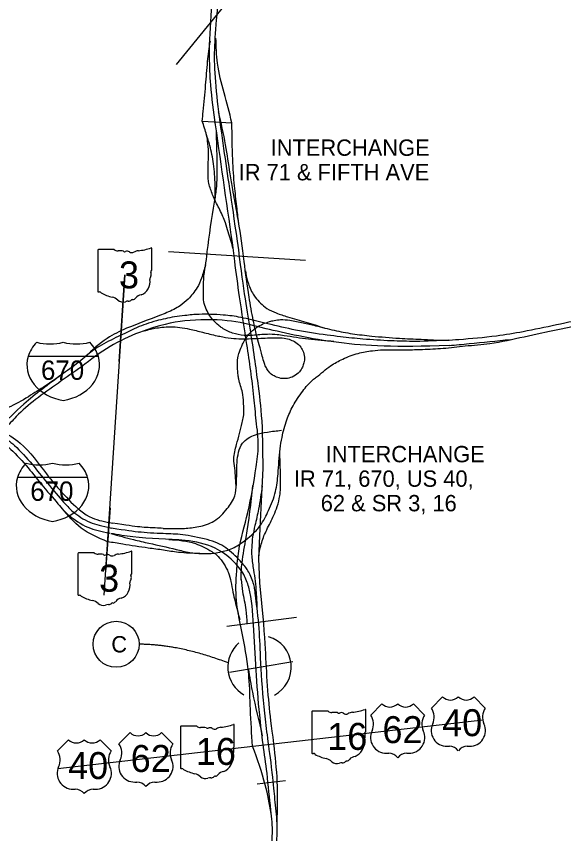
# Model space of a CAD drawing. Extents: x -13 to 322, y -402 to 112.
# Drawn here: x 2.19 to 6.02, y 100.58 to 106.3 of the extents above; entities that cross this region are included whole.
import ezdxf

# ---------------------------------------------------------------- set-up
doc = ezdxf.new("R2010")
doc.units = 0
for name, color, linetype in [('GM_X_Interstate_Shield', 7, 'Continuous'), ('GM_X_State_Shield', 7, 'Continuous'), ('GM_X_US_Shield', 7, 'Continuous'), ('SC_Scratch1', 7, 'Continuous'), ('SH_Data', 7, 'Continuous'), ('SH_Text', 7, 'Continuous')]:
    doc.layers.add(name, color=color, linetype=linetype)

msp = doc.modelspace()

# ---------------------------------------------------------------- linework, layer by layer
at = {"layer": 'GM_X_Interstate_Shield'}
for p, q in [((2.7633, 103.9213), (2.2717, 103.9213)), ((2.7633, 103.9213), (2.2717, 103.9213)), ((2.6884, 103.0745), (2.1967, 103.0745)), ((2.6884, 103.0745), (2.1967, 103.0745))]:
    msp.add_line(p, q, dxfattribs=at)
for centre, start_param, end_param in [((2.581, 103.8632), 2.47259, 2.911027), ((2.4246, 104.264), 4.415841, 5.008937), ((2.6103, 104.264), 4.415841, 5.008937), ((2.4539, 103.8632), 0.230566, 0.669003), ((2.581, 103.8632), 2.911027, 4.511031), ((2.4539, 103.8632), 4.913747, 6.513751), ((2.5061, 103.0164), 2.47259, 2.911027), ((2.3497, 103.4172), 4.415841, 5.008937), ((2.5354, 103.4172), 4.415841, 5.008937), ((2.379, 103.0164), 0.230566, 0.669003), ((2.5061, 103.0164), 2.911027, 4.511031), ((2.379, 103.0164), 4.913747, 6.513751)]:
    msp.add_ellipse(centre, major_axis=(0.3178, 0), ratio=0.8, start_param=start_param, end_param=end_param, dxfattribs=at)
at = {"layer": 'GM_X_State_Shield'}
for p, q in [((2.7595, 104.6646), (2.7595, 104.3781)), ((2.8738, 104.6695), (2.7632, 104.6695)), ((3.137, 104.5267), (3.137, 104.6766)), ((3.137, 104.5268), (3.137, 104.5267)), ((2.6204, 102.5415), (2.6204, 102.255)), ((2.7346, 102.5465), (2.6241, 102.5465)), ((2.9979, 102.4037), (2.9979, 102.5536)), ((2.9978, 102.4037), (2.9979, 102.4037)), ((4.2575, 101.4346), (4.2575, 101.1481)), ((4.3718, 101.4396), (4.2612, 101.4396)), ((4.635, 101.2968), (4.635, 101.4467)), ((3.3375, 101.3293), (3.3375, 101.0427)), ((3.4518, 101.3342), (3.3412, 101.3342)), ((3.715, 101.1914), (3.715, 101.3413)), ((4.635, 101.2968), (4.635, 101.2968)), ((3.715, 101.1914), (3.715, 101.1914))]:
    msp.add_line(p, q, dxfattribs=at)
for centre, radius, start, end in [((3.0025, 105.0601), 0.4003, 275.8445, 288.9065), ((3.1328, 104.6772), 0.0042, 351.8621, 97.738), ((2.7638, 104.6652), 0.00437, 98.1301, 188.1301), ((2.9001, 104.7028), 0.0424, 231.6195, 271.1119), ((2.9142, 104.5087), 0.1523, 80.4867, 94.9883), ((2.9487, 104.6667), 0.0122, 219.7921, 297.1024), ((2.9667, 104.6336), 0.0254, 54.4667, 119.1411), ((2.9995, 104.679), 0.0306, 233.8562, 294.8282), ((3.0536, 104.582), 0.0805, 97.3462, 120.7689), ((3.136, 104.5157), 0.0065, 107.944, 210.337), ((3.0947, 104.4968), 0.039, 340.033, 23.6496), ((3.1325, 104.5261), 0.0045, 289.6038, 7.7341), ((3.025, 104.4449), 0.1001, 292.3089, 8.9858), ((3.1521, 104.464), 0.0284, 136.8065, 186.9296), ((2.7639, 104.3774), 0.00441, 171.9584, 258.3066), ((2.7645, 104.4067), 0.0337, 267.339, 280.6039), ((2.7714, 104.3615), 0.0121, 29.7484, 93.2717), ((2.9247, 104.619), 0.2891, 240.4129, 257.1985), ((2.8385, 104.2493), 0.0905, 47.1842, 75.836), ((3.0672, 104.2976), 0.0548, 94.4031, 142.5768), ((2.9363, 104.3601), 0.0574, 230.7004, 286.2918), ((2.9695, 104.2611), 0.0472, 85.6951, 111.2099), ((2.9737, 104.3387), 0.0306, 268.777, 315.5493), ((3.0014, 104.3109), 0.00861, 65.7517, 132.6484), ((2.9977, 104.3503), 0.0324, 282.8732, 323.2771), ((2.6247, 102.5421), 0.00437, 98.1301, 188.1301), ((2.761, 102.5797), 0.0424, 231.6195, 271.1119), ((2.775, 102.3856), 0.1523, 80.4867, 94.9883), ((2.8096, 102.5436), 0.0122, 219.7921, 297.1024), ((2.8276, 102.5105), 0.0254, 54.4667, 119.1411), ((2.8604, 102.5559), 0.0306, 233.8562, 294.8282), ((2.9145, 102.459), 0.0805, 97.3462, 120.7689), ((2.8634, 102.9371), 0.4003, 275.8445, 288.9065), ((2.9937, 102.5542), 0.0042, 351.8621, 97.738), ((2.9969, 102.3927), 0.0065, 107.944, 210.337), ((2.9934, 102.4031), 0.0045, 289.6038, 7.7341), ((2.8858, 102.3219), 0.1001, 292.3089, 8.9858), ((3.0129, 102.341), 0.0284, 136.8065, 186.9296), ((2.9555, 102.3737), 0.039, 340.033, 23.6496), ((2.6247, 102.2544), 0.00441, 171.9584, 258.3066), ((2.6254, 102.2837), 0.0337, 267.339, 280.6039), ((2.6323, 102.2385), 0.0121, 29.7484, 93.2717), ((2.7856, 102.4959), 0.2891, 240.4129, 257.1985), ((2.928, 102.1746), 0.0548, 94.4031, 142.5768), ((2.6994, 102.1263), 0.0905, 47.1842, 75.836), ((2.7972, 102.2371), 0.0574, 230.7004, 286.2918), ((2.8304, 102.138), 0.0472, 85.6951, 111.2099), ((2.8346, 102.2156), 0.0306, 268.777, 315.5493), ((2.8622, 102.1879), 0.00861, 65.7517, 132.6484), ((2.8586, 102.2273), 0.0324, 282.8732, 323.2771), ((4.2619, 101.4353), 0.00437, 98.1301, 188.1301), ((4.3981, 101.4728), 0.0424, 231.6195, 271.1119), ((4.4122, 101.2787), 0.1523, 80.4867, 94.9883), ((4.4468, 101.4367), 0.0122, 219.7921, 297.1024), ((4.4647, 101.4036), 0.0254, 54.4667, 119.1411), ((4.4976, 101.449), 0.0306, 233.8562, 294.8282), ((4.5516, 101.3521), 0.0805, 97.3462, 120.7689), ((4.5006, 101.8302), 0.4003, 275.8445, 288.9065), ((4.6308, 101.4473), 0.0042, 351.8621, 97.738), ((3.3419, 101.3299), 0.00437, 98.1301, 188.1301), ((3.4781, 101.3675), 0.0424, 231.6195, 271.1119), ((3.4922, 101.1733), 0.1523, 80.4867, 94.9883), ((3.5268, 101.3314), 0.0122, 219.7921, 297.1024), ((3.5447, 101.2982), 0.0254, 54.4667, 119.1411), ((3.5776, 101.3437), 0.0306, 233.8562, 294.8282), ((3.6316, 101.2467), 0.0805, 97.3462, 120.7689), ((3.5806, 101.7248), 0.4003, 275.8445, 288.9065), ((3.7108, 101.3419), 0.0042, 351.8621, 97.738), ((4.6501, 101.2341), 0.0284, 136.8065, 186.9296), ((4.6341, 101.2858), 0.0065, 107.944, 210.337), ((4.5927, 101.2668), 0.039, 340.033, 23.6496), ((4.6305, 101.2962), 0.0045, 289.6038, 7.7341), ((3.7105, 101.1908), 0.0045, 289.6038, 7.7341), ((4.523, 101.215), 0.1001, 292.3089, 8.9858), ((3.7301, 101.1287), 0.0284, 136.8065, 186.9296), ((3.7141, 101.1804), 0.0065, 107.944, 210.337), ((3.6727, 101.1615), 0.039, 340.033, 23.6496), ((4.2619, 101.1475), 0.00441, 171.9584, 258.3066), ((4.2626, 101.1768), 0.0337, 267.339, 280.6039), ((4.2695, 101.1316), 0.0121, 29.7484, 93.2717), ((4.4227, 101.389), 0.2891, 240.4129, 257.1985), ((3.603, 101.1096), 0.1001, 292.3089, 8.9858), ((4.3365, 101.0194), 0.0905, 47.1842, 75.836), ((4.4344, 101.1302), 0.0574, 230.7004, 286.2918), ((4.4675, 101.0311), 0.0472, 85.6951, 111.2099), ((4.4717, 101.1087), 0.0306, 268.777, 315.5493), ((4.4994, 101.081), 0.00861, 65.7517, 132.6484), ((4.4957, 101.1204), 0.0324, 282.8732, 323.2771), ((4.5652, 101.0677), 0.0548, 94.4031, 142.5768), ((3.3419, 101.0421), 0.00441, 171.9584, 258.3066), ((3.3426, 101.0714), 0.0337, 267.339, 280.6039), ((3.3494, 101.0262), 0.0121, 29.7484, 93.2717), ((3.5027, 101.2836), 0.2891, 240.4129, 257.1985), ((3.4165, 100.914), 0.0905, 47.1842, 75.836), ((3.5144, 101.0248), 0.0574, 230.7004, 286.2918), ((3.5475, 100.9257), 0.0472, 85.6951, 111.2099), ((3.5517, 101.0033), 0.0306, 268.777, 315.5493), ((3.5794, 100.9756), 0.00861, 65.7517, 132.6484), ((3.5757, 101.015), 0.0324, 282.8732, 323.2771), ((3.6452, 100.9623), 0.0548, 94.4031, 142.5768)]:
    msp.add_arc(centre, radius, start, end, dxfattribs=at)
at = {"layer": 'GM_X_US_Shield'}
for p, q in [((5.1733, 101.5395), (5.0947, 101.4608)), ((5.4722, 101.4608), (5.3935, 101.5395)), ((4.7487, 101.4908), (4.6701, 101.4122)), ((5.0476, 101.4122), (4.969, 101.4908)), ((2.9861, 101.2889), (2.9075, 101.2103)), ((3.285, 101.2103), (3.2063, 101.2889)), ((2.5547, 101.2395), (2.4761, 101.1609)), ((2.8536, 101.1609), (2.7749, 101.2395)), ((5.2048, 101.1934), (5.2205, 101.1934)), ((5.3464, 101.1934), (5.3621, 101.1934)), ((4.7802, 101.1448), (4.7959, 101.1448)), ((4.9218, 101.1448), (4.9375, 101.1448)), ((3.0176, 100.9429), (3.0333, 100.9429)), ((3.1592, 100.9429), (3.1749, 100.9429)), ((2.5862, 100.8935), (2.6019, 100.8935)), ((2.7277, 100.8935), (2.7434, 100.8935))]:
    msp.add_line(p, q, dxfattribs=at)
for centre, radius, start, end in [((5.2284, 101.5956), 0.0786, 225.573, 314.427), ((5.3385, 101.5956), 0.0786, 225.573, 314.427), ((4.8038, 101.547), 0.0786, 225.573, 314.427), ((4.9139, 101.547), 0.0786, 225.573, 314.427), ((5.0045, 101.3977), 0.1101, 334.5471, 35.0009), ((5.5624, 101.3977), 0.1101, 144.9991, 205.4529), ((4.5799, 101.349), 0.1101, 334.5471, 35.0009), ((5.1378, 101.349), 0.1101, 144.9991, 205.4529), ((5.2036, 101.3035), 0.1101, 154.8319, 270.6383), ((5.3633, 101.3035), 0.1101, 269.3617, 25.1681), ((3.0412, 101.3451), 0.0786, 225.573, 314.427), ((3.1513, 101.3451), 0.0786, 225.573, 314.427), ((4.779, 101.2549), 0.1101, 154.8319, 270.6383), ((4.9387, 101.2549), 0.1101, 269.3617, 25.1681), ((2.6097, 101.2957), 0.0786, 225.573, 314.427), ((2.7199, 101.2957), 0.0786, 225.573, 314.427), ((2.8173, 101.1471), 0.1101, 334.5471, 35.0009), ((3.3752, 101.1471), 0.1101, 144.9991, 205.4529), ((5.2205, 101.1148), 0.0786, 36.8699, 90), ((5.3464, 101.1148), 0.0786, 90, 143.1301), ((2.3859, 101.0977), 0.1101, 334.5471, 35.0009), ((2.9437, 101.0977), 0.1101, 144.9991, 205.4529), ((4.7959, 101.0661), 0.0786, 36.8699, 90), ((4.9218, 101.0661), 0.0786, 90, 143.1301), ((3.0164, 101.053), 0.1101, 154.8319, 270.6383), ((3.1761, 101.053), 0.1101, 269.3617, 25.1681), ((2.5849, 101.0036), 0.1101, 154.8319, 270.6383), ((2.7447, 101.0036), 0.1101, 269.3617, 25.1681), ((3.0333, 100.8642), 0.0786, 36.8699, 90), ((3.1592, 100.8642), 0.0786, 90, 143.1301), ((2.6019, 100.8148), 0.0786, 36.8699, 90), ((2.7277, 100.8148), 0.0786, 90, 143.1301)]:
    msp.add_arc(centre, radius, start, end, dxfattribs=at)
at = {"layer": 'SC_Scratch1'}
for p, q in [((3.9038, 106.6966), (3.3082, 105.9659)), ((3.2542, 104.6557), (4.2144, 104.5967)), ((2.91, 103.8855), (2.9485, 104.4926)), ((2.845, 102.863), (2.8124, 102.4156)), ((3.6616, 102.0342), (4.1516, 102.0974)), ((3.6807, 101.713), (4.125, 101.7859)), ((3.8743, 100.9305), (4.0741, 100.9547))]:
    msp.add_line(p, q, dxfattribs=at)
at = {"layer": 'SH_Data'}
for p, q in [((3.4903, 105.568), (3.6984, 105.5575)), ((2.9485, 104.4926), (2.8017, 102.2512)), ((3.9162, 103.1378), (3.9127, 103.4251)), ((3.9074, 102.9553), (3.9162, 103.1378)), ((3.8958, 102.717), (3.9074, 102.9553)), ((3.8856, 102.5067), (3.8958, 102.717)), ((3.8928, 102.3373), (3.8856, 102.5067)), ((3.921, 102.0537), (3.8928, 102.3373)), ((2.4802, 101.0375), (5.454, 101.3781))]:
    msp.add_line(p, q, dxfattribs=at)
msp.add_circle((2.8876, 101.9075), 0.1612, dxfattribs=at)
for start, end in [(297.8961, 73.2622), (130.6141, 240.4143)]:
    msp.add_arc((3.8916, 101.7479), 0.2221, start, end, dxfattribs=at)
for points in [[(3.7092, 104.6637), (3.5843, 105.5418), (3.5502, 105.8224), (3.5419, 106.018), (3.5884, 106.6724), (3.6232, 107.0317), (3.6255, 107.0682), (3.6713, 107.6752), (3.713, 108.1683), (3.7189, 108.3717), (3.7325, 109.1742), (3.7325, 109.2177), (3.7156, 109.4217), (3.6709, 109.6129), (3.5578, 109.8519), (3.4048, 110.0687), (3.2534, 110.2041), (2.9985, 110.3714), (2.7278, 110.5625), (2.5969, 110.6787), (2.4431, 110.8702), (2.3082, 111.1041), (2.2413, 111.2745), (2.1732, 111.5886), (2.143, 111.8754)], [(3.4903, 105.568), (3.497, 105.6372), (3.5145, 105.8198), (3.5285, 105.9868), (3.5473, 106.1278)], [(3.6984, 105.5575), (3.6441, 105.7663), (3.5969, 105.9737), (3.5868, 106.1503)], [(3.0732, 104.098), (3.1598, 104.1192), (3.2075, 104.1264), (3.2695, 104.1301), (3.3329, 104.1255), (3.4024, 104.1134), (3.4934, 104.0911), (3.5942, 104.0669), (3.6336, 104.059), (3.7118, 104.0481), (3.8486, 104.0471), (3.8863, 104.0486), (4.0082, 104.0531), (4.0636, 104.05), (4.1092, 104.0381), (4.1459, 104.0202), (4.1806, 103.9861), (4.1984, 103.9529), (4.2059, 103.9041), (4.2003, 103.8694), (4.1887, 103.8409), (4.1628, 103.8056), (4.1193, 103.778), (4.0758, 103.7671), (4.0285, 103.7711), (3.9935, 103.7852), (3.9562, 103.8162), (3.9396, 103.8412), (3.9253, 103.8735), (3.9105, 103.9248), (3.8902, 104.0021), (3.8714, 104.0713), (3.8598, 104.1181), (3.8478, 104.1735), (3.8182, 104.3378), (3.784, 104.5863), (3.775, 104.6615), (3.7319, 104.9368), (3.7039, 105.0899), (3.6859, 105.2003), (3.6543, 105.4025), (3.6053, 105.6351)], [(3.7077, 104.6747), (3.6728, 104.7931), (3.6528, 104.8568), (3.6354, 104.9024), (3.5908, 104.9923), (3.5633, 105.0539), (3.5486, 105.0921), (3.5366, 105.1336), (3.5319, 105.1732), (3.5319, 105.2551), (3.534, 105.3505), (3.5282, 105.4311), (3.5202, 105.4728), (3.4903, 105.568)], [(3.745, 104.8597), (3.7325, 104.9717), (3.7167, 105.115), (3.7041, 105.3001), (3.6984, 105.5575)], [(4.4127, 104.0269), (4.2334, 104.0423), (4.1499, 104.0541), (4.0637, 104.0671), (4.0153, 104.0739), (3.9464, 104.0766), (3.8428, 104.0695), (3.7837, 104.0695), (3.7023, 104.085), (3.6294, 104.1211), (3.6063, 104.1386), (3.5648, 104.1792), (3.5377, 104.2169), (3.4994, 104.3185), (3.4994, 104.3534), (3.4994, 104.4403), (3.5223, 104.6239), (3.5258, 104.6556), (3.5772, 105.0023), (3.5903, 105.0961), (3.5955, 105.1787), (3.5955, 105.281), (3.5899, 105.5019)], [(3.5802, 105.0235), (3.5802, 105.1098), (3.5802, 105.1438), (3.5772, 105.1946), (3.57, 105.2691), (3.5583, 105.3349), (3.544, 105.3985), (3.5188, 105.4773)], [(3.8432, 101.1936), (3.8277, 101.4536), (3.8176, 101.6761), (3.8093, 101.7529), (3.7615, 102.031), (3.7303, 102.213), (3.7316, 102.4206), (3.746, 102.5599), (3.8096, 102.8288), (3.8676, 103.1486), (3.8827, 103.2947), (3.8688, 103.4722), (3.8525, 103.6372), (3.8033, 104.0046), (3.752, 104.3388), (3.7181, 104.5896), (3.7092, 104.6637)], [(3.5132, 104.563), (3.4854, 104.4696), (3.4543, 104.4034), (3.4239, 104.3598), (3.3918, 104.3234), (3.3357, 104.2772), (3.2922, 104.2514), (3.1923, 104.2085), (2.9593, 104.119)], [(3.7923, 104.5221), (3.8081, 104.4492), (3.8211, 104.4124), (3.8421, 104.3663), (3.8608, 104.337), (3.8987, 104.2952), (3.9438, 104.2578), (4.0087, 104.2263), (4.0881, 104.1993), (4.2163, 104.1622), (4.3441, 104.1223)], [(5.7366, 104.0966), (6.2025, 104.1954), (6.2366, 104.2032), (6.7716, 104.3142), (7.0008, 104.3573), (7.2204, 104.4039), (7.4472, 104.4308), (7.6169, 104.4443), (7.7236, 104.4498), (7.9501, 104.4482), (7.9803, 104.448), (8.454, 104.4416), (8.7924, 104.47)], [(5.2172, 104.036), (4.9841, 104.0274), (4.8118, 104.0313), (4.616, 104.0433), (4.4576, 104.0599), (4.3658, 104.071), (4.1444, 104.1062), (3.9497, 104.15), (3.909, 104.1588), (3.7598, 104.195), (3.6381, 104.2117), (3.5488, 104.2166), (3.4693, 104.2166), (3.3692, 104.2082), (3.2959, 104.1985), (3.1692, 104.1707), (3.0969, 104.1487), (3.0342, 104.1251)], [(3.7279, 103.0009), (3.718, 103.1396), (3.7119, 103.204), (3.7308, 103.3056), (3.7701, 103.4587), (3.7795, 103.5016), (3.7795, 103.6013), (3.7717, 103.6688), (3.746, 103.7622), (3.7419, 103.7917), (3.7369, 103.8465), (3.7397, 103.9125), (3.7505, 103.9534), (3.7728, 104.007), (3.8146, 104.0747), (3.8726, 104.1264), (3.9621, 104.1658), (3.9939, 104.1739), (4.0395, 104.1795), (4.1037, 104.1756), (4.1965, 104.1571), (4.2825, 104.1372), (4.4148, 104.1051), (4.5417, 104.0811), (4.6771, 104.065), (4.8711, 104.049), (5.0242, 104.0418), (5.1966, 104.0358), (5.2864, 104.0413), (5.5498, 104.067), (5.7366, 104.0966)], [(2.9593, 104.119), (2.8249, 104.0482), (2.6729, 103.9205)], [(3.0507, 104.0903), (2.8452, 103.9921), (2.6446, 103.85), (2.3242, 103.6202), (2.1884, 103.5012), (2.1105, 103.4165), (1.9812, 103.2718), (1.8511, 103.0988), (1.8166, 103.0375), (1.7808, 102.762)], [(2.8506, 102.6829), (3.0086, 102.6404), (3.1175, 102.6147), (3.3073, 102.5719), (3.4031, 102.5499), (3.4872, 102.5422), (3.5741, 102.5456), (3.6262, 102.556), (3.6706, 102.5669), (3.7565, 102.6099), (3.7958, 102.639), (3.8479, 102.6825), (3.8969, 102.7386), (3.9549, 102.8443), (4.0035, 102.9764), (4.021, 103.0995), (4.0362, 103.2751), (4.049, 103.3558), (4.0833, 103.4787), (4.1262, 103.5761), (4.1948, 103.6792), (4.2648, 103.7583), (4.2884, 103.7764), (4.3893, 103.8565), (4.4742, 103.9033), (4.582, 103.9436), (4.6816, 103.9621), (4.758, 103.9684), (4.9195, 103.9684), (5.0323, 103.9715), (5.1765, 103.9791), (5.3314, 103.9954), (5.5048, 104.0136), (5.7443, 104.0602)], [(5.2186, 103.9989), (5.3582, 104.0115), (5.6483, 104.0415)], [(2.5058, 103.7943), (2.2415, 103.5874), (2.069, 103.4227), (1.8432, 103.2095), (1.6978, 103.0844), (1.6183, 103.0156), (1.5573, 102.9294), (1.5301, 102.8538), (1.5259, 102.7991)], [(2.3934, 103.7171), (2.2735, 103.6404), (2.1311, 103.5644), (2.0072, 103.5298), (1.909, 103.5202), (1.7993, 103.5249), (1.7051, 103.5307), (1.6575, 103.5338), (1.6111, 103.5301), (1.571, 103.5252), (1.4128, 103.4896)], [(1.4128, 103.4896), (1.5781, 103.5123), (1.7417, 103.5123), (1.9092, 103.4801), (2.078, 103.4041), (2.2159, 103.3152), (2.4001, 103.1), (2.448, 103.0403), (2.5717, 102.9032), (2.7188, 102.7929), (2.8622, 102.7562)], [(3.2162, 102.7189), (3.3653, 102.7189), (3.4656, 102.731), (3.5723, 102.7696), (3.6655, 102.8576), (3.7182, 102.9463), (3.7301, 103.0263), (3.7347, 103.1808), (3.773, 103.3142), (3.8626, 103.3735), (3.9463, 103.3927), (4.0447, 103.4053)], [(3.8862, 102.5184), (3.9067, 102.6209), (3.9424, 102.709), (3.9917, 102.8102), (4.0155, 102.8715), (4.0333, 102.9469), (4.0391, 103.0514), (4.0332, 103.2453)], [(3.7641, 102.3574), (3.7644, 102.4229), (3.7693, 102.4766), (3.7981, 102.6556), (3.8454, 103.0177)], [(3.9103, 103.0162), (3.885, 102.8532), (3.8599, 102.7392), (3.8434, 102.6596), (3.837, 102.583), (3.837, 102.524), (3.8496, 102.428), (3.8681, 102.2691), (3.8733, 102.1637)], [(2.8277, 102.6253), (2.6421, 102.7211), (2.5099, 102.8589)], [(3.9442, 101.0053), (3.8927, 101.4127), (3.8496, 102.0434), (3.8157, 102.3067), (3.7814, 102.3955), (3.7068, 102.4895), (3.5799, 102.5807), (3.3719, 102.6336), (3.0042, 102.6586), (2.8506, 102.6829)], [(3.4728, 102.5427), (3.3235, 102.5508), (3.2191, 102.5658), (3.1129, 102.5806), (2.9341, 102.6077), (2.8277, 102.6253)], [(3.2578, 102.6412), (3.4427, 102.6122), (3.5569, 102.5562), (3.5901, 102.5334), (3.6318, 102.4848), (3.6667, 102.4257), (3.6744, 102.4079), (3.6918, 102.3459), (3.7056, 102.2725), (3.7202, 102.2086), (3.753, 102.0803)], [(3.7638, 102.3606), (3.7728, 102.277), (3.7962, 102.1484), (3.8027, 102.0524)], [(3.8121, 101.7346), (3.8418, 101.5717), (3.9112, 101.2664)], [(3.9739, 100.7237), (3.9321, 100.9226), (3.8432, 101.1936)], [(4.0145, 100.656), (4.0157, 100.9476), (3.9922, 101.2107)], [(3.9713, 100.4643), (3.9818, 100.5824), (3.9714, 100.7456), (3.9442, 101.0053)]]:
    msp.add_spline(points, degree=3, dxfattribs=at)
for points, degree in [([(3.746, 104.6689), (3.7, 104.9919), (3.6496, 105.3161), (3.5602, 105.9597), (3.5923, 106.2792), (3.6806, 107.2532), (3.7425, 107.9064), (3.7649, 108.7199), (3.7698, 108.883), (3.7702, 109.2113), (3.7707, 109.3812), (3.6831, 109.7044), (3.6074, 109.8565), (3.4132, 110.1323), (3.2743, 110.2359), (3.0026, 110.4169), (2.862, 110.5067), (2.6127, 110.6968), (2.512, 110.8246), (2.2567, 111.2315), (2.2141, 111.5548), (2.1799, 111.8793)], 3), ([(3.9127, 103.4251), (3.9039, 103.5509), (3.8898, 103.676), (3.834, 104.0914), (3.7807, 104.3798), (3.7461, 104.6681)], 3), ([(5.7443, 104.0602), (6.2483, 104.1672), (6.7605, 104.2916), (7.7512, 104.454), (8.2821, 104.39), (8.7955, 104.433)], 3), ([(5.2186, 103.9989), (4.8391, 103.9849), (4.4423, 104.0018), (3.8736, 104.128), (3.6902, 104.1811), (3.3509, 104.1807), (3.2001, 104.1421), (3.0507, 104.0903)], 3), ([(3.0347, 104.1238), (2.9625, 104.0893), (2.894, 104.059), (2.7402, 103.9801), (2.6784, 103.9237), (2.5452, 103.8191), (2.4689, 103.7696), (2.3934, 103.7171)], 3), ([(1.4228, 103.4535), (1.5642, 103.4729), (1.7012, 103.4907), (1.8983, 103.4448), (1.9636, 103.4199), (2.0899, 103.3575), (2.1491, 103.3319), (2.2958, 103.1766), (2.3805, 103.0627), (2.5242, 102.8979), (2.5735, 102.8402), (2.7038, 102.7498), (2.7881, 102.7369), (2.853, 102.7203)], 3), ([(1.9871, 103.3665), (1.9948, 103.363), (2.0025, 103.3593), (2.0745, 103.3237), (2.1231, 103.3053), (2.2668, 103.1533), (2.3529, 103.0378), (2.4961, 102.8737), (2.5427, 102.8163), (2.6922, 102.7127), (2.7819, 102.7001), (2.8438, 102.6843)], 3), ([(3.2162, 102.7189), (3.1951, 102.7198), (3.1744, 102.7206), (3.0564, 102.7261), (2.9632, 102.7403), (2.8622, 102.7562)], 3), ([(3.9811, 101.01), (3.9558, 101.2099), (3.9255, 101.4089), (3.8968, 101.8078), (3.8937, 102.0104), (3.8607, 102.264), (3.8572, 102.3176), (3.8144, 102.4231), (3.7794, 102.4678), (3.6673, 102.5843), (3.5611, 102.6355), (3.3553, 102.6781), (3.2523, 102.6798), (3.0522, 102.6891), (2.9575, 102.7036), (2.8564, 102.7196)], 3), ([(3.9922, 101.2107), (3.9746, 101.3446), (3.9578, 101.4777), (3.9378, 101.7548), (3.9328, 101.9063), (3.921, 102.0537)], 3), ([(3.6715, 101.7773), (3.3262, 101.9075), (3.0487, 101.9075)], 2), ([(4.0059, 100.4624), (4.016, 100.5475), (4.019, 100.6494), (3.9981, 100.8295), (3.9907, 100.9186), (3.9812, 101.0092)], 3)]:
    msp.add_open_spline(points, degree=degree, dxfattribs=at)

# ---------------------------------------------------------------- texts
at = {"layer": 'GM_X_Interstate_Shield'}
for p in [(2.3616, 103.7582), (2.2867, 102.9114)]:
    msp.add_text('670', height=0.13558, dxfattribs=at).set_placement(p)
at = {"layer": 'GM_X_State_Shield'}
for s, height, p in [('3', 0.1888, (2.9075, 104.3983)), ('3', 0.1888, (2.7684, 102.2752)), ('16', 0.18875, (4.3652, 101.1683)), ('16', 0.18875, (3.4452, 101.063))]:
    msp.add_text(s, height=height, dxfattribs=at).set_placement(p)
at = {"layer": 'GM_X_US_Shield'}
for s, p in [('40', (5.1701, 101.2642)), ('62', (4.752, 101.2156)), ('62', (2.9894, 101.0137)), ('40', (2.5514, 100.9643))]:
    msp.add_text(s, height=0.18875, dxfattribs=at).set_placement(p)
at = {"layer": 'SH_Data'}
msp.add_text('C', height=0.1144, dxfattribs=at).set_placement((2.8538, 101.8503))
at = {"layer": 'SH_Text'}
for s, p in [('INTERCHANGE', (3.9695, 105.3261)), ('IR 71 & FIFTH AVE', (3.7457, 105.1545)), ('INTERCHANGE', (4.3553, 103.1812)), ('IR 71, 670, US 40,', (4.1324, 103.0097)), ('62 & SR 3, 16', (4.3202, 102.8381))]:
    msp.add_text(s, height=0.114366, dxfattribs=at).set_placement(p)

doc.saveas('drawing.dxf')
